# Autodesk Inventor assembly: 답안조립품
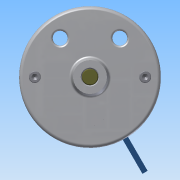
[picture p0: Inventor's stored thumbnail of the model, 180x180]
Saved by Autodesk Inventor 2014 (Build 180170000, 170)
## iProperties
Created: 2015-07
Part Number: 답안조립품
Document SubType Name: Assembly
Designer: Administrator
Author: Administrator
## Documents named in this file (10)
- C:\Documents and Settings\Administrator\바탕 화면\450631V1011\답안조립품.iam
- C:\Documents and Settings\Administrator\바탕 화면\450631V1011\1-본체.ipt
- C:\Documents and Settings\Administrator\바탕 화면\450631V1011\베어링62_22.ipt
- C:\Documents and Settings\Administrator\바탕 화면\450631V1011\축.ipt
- C:\Documents and Settings\Administrator\바탕 화면\450631V1011\멈춤링.ipt
- C:\Documents and Settings\Administrator\바탕 화면\450631V1011\슬라이더2.ipt
- C:\Documents and Settings\Administrator\바탕 화면\450631V1011\슬라이더.ipt
- C:\Documents and Settings\Administrator\바탕 화면\450631V1011\평행핀.ipt
- C:\Documents and Settings\Administrator\바탕 화면\450631V1011\덮개.ipt
- C:\Documents and Settings\Administrator\바탕 화면\450631V1011\M10x35.ipt
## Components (8 placed, 5 different names)
1. 1-본체:1
2. KS B 2023 62/22 - 22 x 50 x 14:1
3. KS B 1336 22 x 1.2:2
4. KS B 1336 22 x 1.2:3
5. KS B 1320 B B 5 x  20:1
6. KS B 2023 62/22 - 22 x 50 x 14:2
7. KS B 1003 - 미터 M 10 x 35:1
8. KS B 1003 - 미터 M 10 x 35:2
